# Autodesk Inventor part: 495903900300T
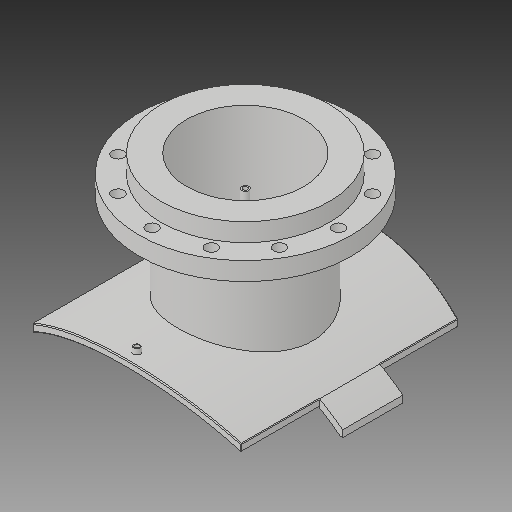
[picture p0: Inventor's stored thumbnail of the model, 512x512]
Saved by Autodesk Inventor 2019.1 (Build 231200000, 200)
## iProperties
Created: 2017-10
Part Number: 495903900300T
Material: Generic
Description: PLASSON FLANGED BRANCH SADDLE 900X300
Document SubType Name: Modeling
Designer: KIM
Mass: 2339.99 g
Surface Area: 3251.55 cm^2
Volume: 2339.99 cm^3
Density: 1 g/cm^3
Appearance: Default
Author: KIM
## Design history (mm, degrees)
derived "495904_495903.ipt"
feature "Solid1::495904_495903.ipt"
feature "Solid2::495904_495903.ipt"
tag "TaggingFeature1"
body "Solid1"
other parameters: "d1" = 15, "d2" = 459, "d4" = 0, "d6" = 132.5, "d7" = 0, "d12" = 475.6, "d13" = 14, "d14" = 238.5, "d16" = 5 deg, "d18" = 4, "d19" = 14, "d20" = 0, "d21" = 3, "d22" = 0, "d36" = 238.5, "d38" = 0, "d39" = 2, "d41" = 257, "d43" = 467, "d46" = 296, "d47" = 16, "d48" = 10.4, "d49" = 192.5, "d51" = 918, "d53" = 0, "d54" = 26, "d55" = 205, "d57" = 0, "d59" = 360 deg, "d63" = 0, "d66" = 275, "d67" = 15, "d68" = 137.5, "d70" = 0, "d71" = 2, "H_" = 275, "x_" = 15, "D_" = 16, "DN_" = 257, "D_1" = 467, "s_" = 26
